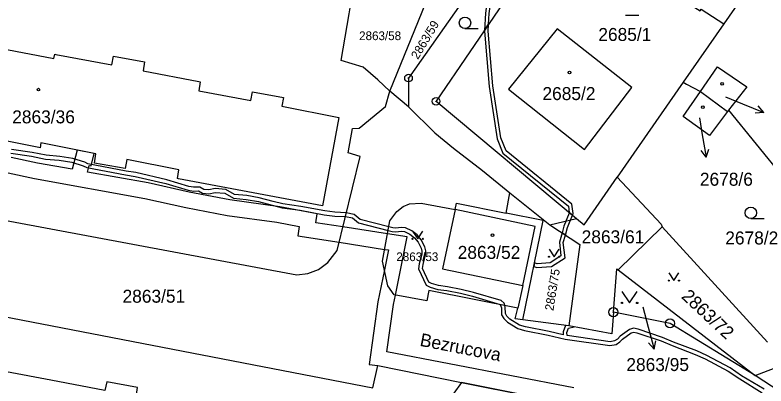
# Model space of a CAD drawing. Extents: x -644096 to -634268, y -1141430 to -1133463.
# Drawn here: x -639716.7 to -639618.2, y -1138556.7 to -1138508.1 of the extents above; entities that cross this region are included whole.
import ezdxf

# ---------------------------------------------------------------- set-up
doc = ezdxf.new("R2010")
doc.units = 0
for name, color, linetype in [('_CIVIL_CONSTRUCTION', 7, 'Continuous'), ('B_Hranice _3D', 7, 'Continuous'), ('M_Svah_Nasyp', 7, 'Continuous'), ('M_Svah_Zarez', 7, 'Continuous'), ('svrsek_osa_sjezdy', 7, 'Continuous'), ('svrsek_osa_terminal_VRT', 7, 'Continuous'), ('svrsek_osa_VRT', 7, 'Continuous'), ('svrsek_popisy_VRT', 7, 'Continuous'), ('terminal_VRT', 7, 'Continuous')]:
    doc.layers.add(name, color=color, linetype=linetype)

msp = doc.modelspace()

# ---------------------------------------------------------------- linework, layer by layer
at = {"layer": '_CIVIL_CONSTRUCTION'}
for centre, radius in [((-639665.06, -1138516.37), 0.5), ((-639665.06, -1138516.37), 0.0303), ((-639661.44, -1138519.41), 0.5), ((-639661.44, -1138519.41), 0.0303), ((-639638.18, -1138547.03), 0.6), ((-639638.18, -1138547.03), 0.0364), ((-639630.75, -1138548.49), 0.6), ((-639630.75, -1138548.49), 0.0364)]:
    msp.add_circle(centre, radius, dxfattribs=at)
at = {"layer": 'B_Hranice _3D'}
for points in [[(-639634.15, -1138474.22), (-639637.55, -1138479.1), (-639640.75, -1138484.5), (-639653.84, -1138503.16), (-639654.62, -1138505.21), (-639654.98, -1138507.86), (-639655.1, -1138510.12), (-639654.55, -1138509.32), (-639654.48, -1138507.9), (-639654.14, -1138505.33), (-639653.4, -1138503.4), (-639640.33, -1138484.78), (-639637.13, -1138479.38), (-639633.77, -1138474.54), (-639632.31, -1138473.08), (-639632, -1138472.48), (-639632.54, -1138471.89), (-639632.45, -1138472.25), (-639632.71, -1138472.78)], [(-639643.54, -1138534.32), (-639643.45, -1138534.11), (-639643.63, -1138532.88), (-639652.25, -1138525.88), (-639652.94, -1138524.18), (-639653.98, -1138517.39), (-639654.6, -1138510.21), (-639654.55, -1138509.32), (-639655.1, -1138510.12), (-639655.1, -1138510.21), (-639654.48, -1138517.45), (-639653.42, -1138524.32), (-639652.67, -1138526.18), (-639644.09, -1138533.14), (-639643.98, -1138533.95)], [(-639644.48, -1138536.94), (-639644.19, -1138535.94), (-639643.54, -1138534.32), (-639643.98, -1138533.95), (-639643.97, -1138534.05), (-639644.67, -1138535.78), (-639644.92, -1138536.65)], [(-639646.3, -1138541.03), (-639644.52, -1138539.91), (-639644.76, -1138537.88), (-639644.48, -1138536.94), (-639644.92, -1138536.65), (-639645.26, -1138537.84), (-639645.06, -1138539.65), (-639646.46, -1138540.55), (-639648.18, -1138540.68), (-639648.54, -1138540.57), (-639648.64, -1138541.06), (-639648.24, -1138541.18)]]:
    msp.add_lwpolyline(points, close=True, dxfattribs=at)
for points in [[(-639643.38, -1138556.94), (-639667.92, -1138552.22), (-639667.03, -1138546.02), (-639666.78, -1138544.8), (-639665.25, -1138537.18), (-639667.81, -1138536.78), (-639673.67, -1138535.86), (-639677.21, -1138535.31), (-639677.02, -1138534.13), (-639681.95, -1138533.22), (-639688.5, -1138532.31), (-639693.82, -1138531.31), (-639699.2, -1138530.1), (-639707.15, -1138528.67), (-639706.94, -1138527.82), (-639706.68, -1138527.88), (-639706.3, -1138526.25), (-639708.54, -1138525.8), (-639709.16, -1138528.3), (-639713.71, -1138527.52), (-639717.17, -1138526.76)], [(-639618.39, -1138557.13), (-639621.36, -1138555.35), (-639622.87, -1138554.32), (-639625.91, -1138552.69), (-639627.26, -1138552.11), (-639630.29, -1138550.95), (-639631.74, -1138550.34), (-639634.95, -1138549.25), (-639635.54, -1138549.12), (-639636.06, -1138549.28), (-639637.31, -1138550.17), (-639637.65, -1138550.55), (-639638.05, -1138550.79), (-639638.59, -1138550.91), (-639644.25, -1138550.1), (-639644.29, -1138549.67), (-639644.06, -1138549.12), (-639643.32, -1138548.95), (-639644.02, -1138548.82), (-639644.45, -1138548.76), (-639644.79, -1138549.59), (-639644.76, -1138550.01), (-639646.63, -1138549.54), (-639649.73, -1138548.93), (-639650.48, -1138548.72), (-639651.76, -1138547.95), (-639652.16, -1138547.57), (-639652.35, -1138547.22), (-639652.38, -1138546.39), (-639652.44, -1138546.15), (-639652.52, -1138545.84), (-639652.9, -1138545.49), (-639656.54, -1138544.43), (-639658.13, -1138544.04), (-639659.96, -1138543.7), (-639661.11, -1138543.55), (-639662.03, -1138543.27), (-639662.4, -1138543.1), (-639663.21, -1138541.29), (-639663.15, -1138540.79), (-639662.83, -1138539.53), (-639662.8, -1138539.01), (-639662.9, -1138538.47), (-639663.38, -1138537.57), (-639663.92, -1138536.91), (-639664.63, -1138536.39), (-639665.45, -1138536), (-639666.04, -1138535.93), (-639666.74, -1138536.01), (-639667.12, -1138535.98), (-639667.63, -1138535.85), (-639671.4, -1138534.88), (-639672.19, -1138534.23), (-639673.22, -1138534.02), (-639674.7, -1138533.94), (-639676.02, -1138533.77), (-639679.17, -1138533.18), (-639681.53, -1138532.85), (-639682.8, -1138532.51), (-639684.65, -1138532.04), (-639686.28, -1138531.75), (-639687.88, -1138531.61), (-639689.02, -1138530.98), (-639690.42, -1138530.85), (-639691.27, -1138531.02), (-639691.9, -1138530.97), (-639692.45, -1138530.65), (-639693.24, -1138530.66), (-639693.85, -1138530.57), (-639696.75, -1138529.68), (-639700.81, -1138528.74), (-639702.09, -1138528.56), (-639707.11, -1138527.59), (-639707.53, -1138527.4), (-639709.1, -1138526.92), (-639710.81, -1138526.63), (-639712.6, -1138526.47), (-639714.43, -1138526.1), (-639717.15, -1138525.72)], [(-639717.23, -1138526.22), (-639714.51, -1138526.6), (-639712.68, -1138526.97), (-639710.87, -1138527.13), (-639709.22, -1138527.4), (-639707.71, -1138527.86), (-639707.27, -1138528.07), (-639702.17, -1138529.06), (-639700.91, -1138529.24), (-639696.89, -1138530.16), (-639693.97, -1138531.05), (-639693.28, -1138531.16), (-639692.59, -1138531.15), (-639692.06, -1138531.45), (-639691.25, -1138531.52), (-639690.4, -1138531.35), (-639689.16, -1138531.46), (-639688.03, -1138532.09), (-639686.34, -1138532.25), (-639684.75, -1138532.52), (-639682.92, -1138532.99), (-639681.63, -1138533.35), (-639679.25, -1138533.68), (-639676.1, -1138534.27), (-639674.74, -1138534.44), (-639673.34, -1138534.5), (-639672.41, -1138534.69), (-639671.62, -1138535.34), (-639667.73, -1138536.34), (-639667.2, -1138536.48), (-639666.72, -1138536.51), (-639666.04, -1138536.43), (-639665.59, -1138536.48), (-639664.89, -1138536.83), (-639664.26, -1138537.27), (-639663.8, -1138537.85), (-639663.38, -1138538.63), (-639663.3, -1138539.05), (-639663.33, -1138539.45), (-639663.65, -1138540.69), (-639663.73, -1138541.37), (-639662.76, -1138543.48), (-639662.21, -1138543.73), (-639661.21, -1138544.04), (-639660.04, -1138544.2), (-639658.23, -1138544.52), (-639656.68, -1138544.91), (-639653.04, -1138546.03), (-639652.88, -1138546.45), (-639652.85, -1138547.36), (-639652.56, -1138547.87), (-639652.06, -1138548.35), (-639650.7, -1138549.18), (-639649.85, -1138549.41), (-639646.73, -1138550.02), (-639644.52, -1138550.57), (-639638.63, -1138551.41), (-639637.83, -1138551.25), (-639637.33, -1138550.93), (-639636.97, -1138550.55), (-639635.84, -1138549.74), (-639635.52, -1138549.64), (-639635.09, -1138549.73), (-639631.92, -1138550.8), (-639630.47, -1138551.41), (-639627.44, -1138552.57), (-639626.13, -1138553.15), (-639623.13, -1138554.74), (-639621.62, -1138555.77), (-639618.65, -1138557.57)], [(-639717.55, -1138528.78), (-639714.11, -1138529.54), (-639699.64, -1138532.12), (-639694.26, -1138533.33), (-639688.84, -1138534.35), (-639682.31, -1138535.24), (-639679.38, -1138535.79), (-639679.59, -1138537.03), (-639674.17, -1138537.87), (-639668.19, -1138538.8), (-639667.69, -1138538.88), (-639668.22, -1138541.49), (-639669.07, -1138545.66), (-639670.24, -1138553.88), (-639669.09, -1138554.03), (-639658.11, -1138556.23), (-639639.64, -1138559.9)]]:
    msp.add_lwpolyline(points, dxfattribs=at)
at = {"layer": 'M_Svah_Nasyp'}
for p, q in [((-639648.43, -1138535.79), (-639658.93, -1138533.6)), ((-639650.06, -1138543.53), (-639648.43, -1138535.79))]:
    msp.add_line(p, q, dxfattribs=at)
at = {"layer": 'M_Svah_Zarez'}
for centre in [(-639643.927, -1138515.639), (-639623.937, -1138517.129), (-639713.607, -1138517.879), (-639626.447, -1138520.179), (-639654.047, -1138536.939)]:
    msp.add_circle(centre, 0.175, dxfattribs=at)
at = {"layer": 'svrsek_osa_sjezdy'}
for p, q in [((-639636.583, -1138508.11), (-639634.833, -1138508.11)), ((-639657.653, -1138509.88), (-639655.903, -1138509.88)), ((-639620.153, -1138534.77), (-639618.403, -1138534.77))]:
    msp.add_line(p, q, dxfattribs=at)
for points in [[(-639664.52, -1138536.414), (-639663.85, -1138537.42), (-639663.18, -1138536.414)], [(-639646.63, -1138538.764), (-639645.96, -1138539.77), (-639645.29, -1138538.764)], [(-639630.92, -1138541.874), (-639630.25, -1138542.88), (-639629.58, -1138541.874)], [(-639637.07, -1138544.309), (-639636.07, -1138545.81), (-639635.07, -1138544.309)]]:
    msp.add_lwpolyline(points, dxfattribs=at)
for centre, radius in [((-639657.653, -1138509.13), 0.75), ((-639620.153, -1138534.02), 0.75), ((-639664.52, -1138537.42), 0.067), ((-639663.18, -1138537.42), 0.067), ((-639646.63, -1138539.77), 0.067), ((-639645.29, -1138539.77), 0.067), ((-639630.92, -1138542.88), 0.067), ((-639629.58, -1138542.88), 0.067), ((-639637.07, -1138545.809), 0.1), ((-639635.07, -1138545.809), 0.1)]:
    msp.add_circle(centre, radius, dxfattribs=at)
at = {"layer": 'svrsek_osa_terminal_VRT'}
msp.add_arc((-642050.261, -1145189.597), 8802.25, 41.4131519, 75.3170489, dxfattribs=at)
at = {"layer": 'svrsek_popisy_VRT'}
for p, q in [((-639623.48, -1138518.82), (-639621.25, -1138519.73)), ((-639621.25, -1138519.73), (-639618.468, -1138520.854)), ((-639618.468, -1138520.854), (-639619.208, -1138520.015)), ((-639618.468, -1138520.854), (-639619.584, -1138520.943)), ((-639626.89, -1138521.58), (-639626.52, -1138523.78)), ((-639626.52, -1138523.78), (-639625.999, -1138526.735)), ((-639625.999, -1138526.735), (-639626.666, -1138525.836)), ((-639625.999, -1138526.735), (-639625.68, -1138525.662)), ((-639634.34, -1138546.32), (-639633.61, -1138548.99)), ((-639633.61, -1138548.99), (-639632.833, -1138551.889)), ((-639632.833, -1138551.889), (-639633.576, -1138551.051)), ((-639632.833, -1138551.889), (-639632.609, -1138550.792))]:
    msp.add_line(p, q, dxfattribs=at)
at = {"layer": 'terminal_VRT'}
for p, q in [((-639620.38, -1138504.5), (-639623.68, -1138509.25)), ((-639667.5, -1138518.07), (-639662.78, -1138506.49)), ((-639623.68, -1138509.25), (-639629.03, -1138516.92)), ((-639629.03, -1138516.92), (-639637.67, -1138529.34)), ((-639665.07, -1138520.13), (-639667.5, -1138518.07)), ((-639626.78, -1138518.12), (-639623.2, -1138520.73)), ((-639623.08, -1138520.57), (-639623.2, -1138520.73)), ((-639623.08, -1138520.57), (-639607.23, -1138540.12)), ((-639652.25, -1138534.06), (-639651.75, -1138531.39)), ((-639651.75, -1138531.39), (-639646.54, -1138535.6)), ((-639646.54, -1138535.6), (-639643.02, -1138534.75)), ((-639637.57, -1138541.47), (-639631.77, -1138535.85)), ((-639631.77, -1138535.85), (-639617.95, -1138550.97)), ((-639637.57, -1138541.47), (-639619.59, -1138555.32)), ((-639644.02, -1138548.82), (-639650.07, -1138548.03)), ((-639619.59, -1138555.32), (-639615.47, -1138553.71)), ((-639658.11, -1138556.23), (-639665.42, -1138566.42)), ((-639639.64, -1138559.9), (-639658.11, -1138556.23))]:
    msp.add_line(p, q, dxfattribs=at)
for points in [[(-639630.51, -1138474.11), (-639661.44, -1138519.41), (-639643.02, -1138534.75)], [(-639619.92, -1138485.29), (-639621.75, -1138487.15), (-639623.42, -1138486.03), (-639622.91, -1138485.27), (-639631.25, -1138479.55), (-639636.9, -1138487.84), (-639644.22, -1138498.58), (-639641.75, -1138500.26), (-639642.42, -1138501.26), (-639640.03, -1138502.9), (-639638.31, -1138500.32), (-639626.82, -1138507.56), (-639626.69, -1138507.35), (-639623.68, -1138509.25)], [(-639667.5, -1138518.07), (-639669.09, -1138516.61), (-639671, -1138514.94), (-639673.88, -1138514.08), (-639672.86, -1138507.95), (-639672.49, -1138505.8)], [(-639658.21, -1138506.63), (-639665.06, -1138516.37), (-639665.07, -1138520.13)], [(-639645.55, -1138509.91), (-639651.94, -1138517.81), (-639641.96, -1138525.73), (-639635.75, -1138517.62), (-639645.55, -1138509.91)], [(-639718.72, -1138512.47), (-639711.57, -1138513.82), (-639711.46, -1138513.23), (-639711.31, -1138513.26), (-639703.97, -1138514.63), (-639703.75, -1138513.48), (-639699.68, -1138514.25), (-639699.86, -1138515.41), (-639692.54, -1138516.82), (-639692.39, -1138516.85), (-639692.55, -1138518.02), (-639685.76, -1138519.32)], [(-639626.78, -1138518.12), (-639624.54, -1138514.88), (-639620.7, -1138517.5), (-639623.08, -1138520.57)], [(-639629.03, -1138516.92), (-639628.59, -1138517.15), (-639626.78, -1138518.12)], [(-639754.35, -1138528.22), (-639679.72, -1138542.13), (-639678.26, -1138541.96), (-639676.88, -1138541.42), (-639675.65, -1138540.52), (-639674.43, -1138538.95), (-639671.42, -1138526.65), (-639672.97, -1138526.16), (-639672.41, -1138522.98), (-639671.54, -1138522.93), (-639668.06, -1138520.08), (-639667.5, -1138518.07)], [(-639623.2, -1138520.73), (-639625.59, -1138523.87), (-639629.05, -1138521.39), (-639626.78, -1138518.12)], [(-639685.76, -1138519.32), (-639685.51, -1138518.18), (-639681.46, -1138518.9), (-639681.66, -1138520.05), (-639674.18, -1138521.53), (-639676.33, -1138533.1), (-639695.22, -1138529.55), (-639695.37, -1138529.52), (-639695.18, -1138528.38), (-639701.99, -1138527.04), (-639702.22, -1138528.22), (-639706.24, -1138527.49), (-639706.08, -1138526.29), (-639713.28, -1138524.86), (-639713.38, -1138525.49), (-639713.53, -1138525.46), (-639720.82, -1138524.03)], [(-639665.07, -1138520.13), (-639661.59, -1138523.52), (-639659.14, -1138525.53), (-639655.37, -1138528.46), (-639651.75, -1138531.39)], [(-639643.02, -1138534.75), (-639642.01, -1138535.58), (-639637.67, -1138529.34)], [(-639637.67, -1138529.34), (-639631.93, -1138535.5), (-639631.77, -1138535.85)], [(-639650.73, -1138546.49), (-639662.41, -1138544.19), (-639662.64, -1138545.54), (-639666.94, -1138544.77), (-639667.75, -1138543.59), (-639668.48, -1138540.35), (-639667.49, -1138535.08), (-639666.6, -1138533.83), (-639665.74, -1138533.19), (-639664.93, -1138532.85), (-639663.39, -1138532.77), (-639658.93, -1138533.6)], [(-639658.93, -1138533.6), (-639658.76, -1138532.74), (-639652.25, -1138534.06)], [(-639658.93, -1138533.6), (-639660.59, -1138541.34), (-639650.06, -1138543.53), (-639650.73, -1138546.49)], [(-639650.07, -1138548.03), (-639647.41, -1138535.04), (-639652.25, -1138534.06)], [(-639646.54, -1138535.6), (-639642.57, -1138538.18), (-639644.02, -1138548.82)], [(-639638.18, -1138547.03), (-639637.75, -1138541.35), (-639637.57, -1138541.47)], [(-639735.59, -1138544.25), (-639669.75, -1138556.92), (-639669.09, -1138554.03), (-639658.11, -1138556.23)], [(-639650.07, -1138548.03), (-639651.05, -1138547.9), (-639650.73, -1138546.49)], [(-639638.18, -1138547.03), (-639638.39, -1138549.88), (-639644.02, -1138548.82)], [(-639619.59, -1138555.32), (-639630.75, -1138548.49), (-639638.18, -1138547.03)], [(-639722.76, -1138552.66), (-639726.74, -1138551.91), (-639727.02, -1138553.06), (-639734.44, -1138551.65), (-639736.7, -1138563.18), (-639717.96, -1138566.73), (-639695.66, -1138570.96), (-639695.48, -1138570.36), (-639677.12, -1138573.93), (-639675.09, -1138562.33), (-639682.38, -1138560.93), (-639682.18, -1138559.79), (-639686.26, -1138559.09), (-639686.35, -1138560.22), (-639693.68, -1138558.86), (-639693.83, -1138558.83), (-639693.99, -1138559.4), (-639700.8, -1138558.11), (-639700.62, -1138556.9), (-639704.61, -1138556.14), (-639704.89, -1138557.3), (-639711.98, -1138555.95), (-639722.93, -1138553.86), (-639722.76, -1138552.66)], [(-639604.49, -1138565.73), (-639607.63, -1138563.15), (-639619.59, -1138555.32)]]:
    msp.add_lwpolyline(points, dxfattribs=at)

# ---------------------------------------------------------------- texts
at = {"layer": 'svrsek_osa_VRT'}
for s, height, rotation, p in [('2863/59', 1.14, 59, (-639663.83, -1138514.001)), ('2863/75', 1.14, 81, (-639646.058, -1138546.897)), ('2863/72', 1.7, 317, (-639629.365, -1138545.096))]:
    msp.add_text(s, height=height, rotation=rotation, dxfattribs=at).set_placement(p)
for s, height, p in [('2863/58', 1.14, (-639671.537, -1138511.395)), ('2685/1', 1.7, (-639640.16, -1138511.505)), ('2685/2', 1.7, (-639647.49, -1138519.245)), ('2863/36', 1.7, (-639717.036, -1138522.295)), ('2678/6', 1.7, (-639626.84, -1138530.465)), ('2863/61', 1.7, (-639642.346, -1138538.005)), ('2678/2', 1.7, (-639623.51, -1138538.155)), ('2863/52', 1.7, (-639658.606, -1138540.045)), ('2863/53', 1.14, (-639666.657, -1138540.335)), ('2863/51', 1.7, (-639702.566, -1138545.785)), ('2863/95', 1.7, (-639636.486, -1138554.735))]:
    msp.add_text(s, height=height, dxfattribs=at).set_placement(p)
at = {"layer": 'svrsek_popisy_VRT'}
msp.add_text('Bezrucova', height=1.7, rotation=349, dxfattribs=at).set_placement((-639663.657, -1138551.425))

doc.saveas('drawing.dxf')
